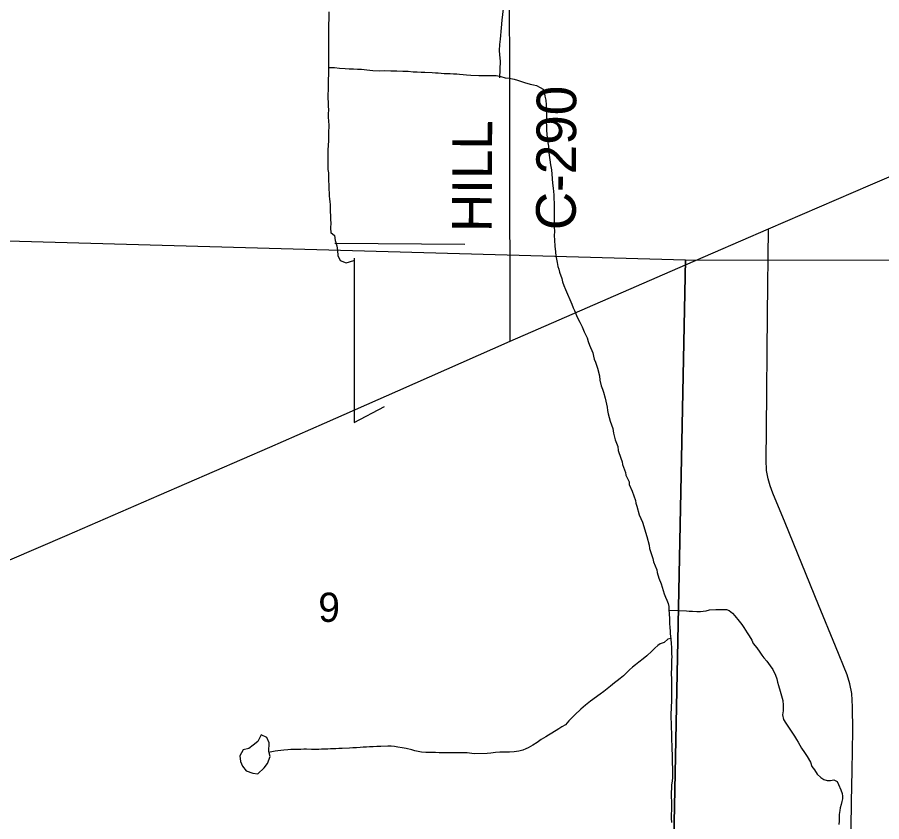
# Model space of a CAD drawing. Extents: x 0 to 34, y 0 to 22.
# Drawn here: x 4.264 to 4.883, y 14.576 to 15.153 of the extents above; entities that cross this region are included whole.
import ezdxf

# ---------------------------------------------------------------- set-up
doc = ezdxf.new("R2010")
doc.units = 0
for name, color, linetype in [('GM_X_Corporation', 7, 'Continuous'), ('GM_X_County_Road', 7, 'Continuous'), ('GM_X_County_Road_Text', 7, 'Continuous'), ('GM_X_Minor_Lake', 7, 'Continuous'), ('GM_X_Minor_River', 7, 'Continuous'), ('GM_X_Section_Text', 7, 'Continuous'), ('GM_X_US_Route', 7, 'Continuous')]:
    doc.layers.add(name, color=color, linetype=linetype)

msp = doc.modelspace()

# ---------------------------------------------------------------- linework, layer by layer
at = {"layer": 'GM_X_Corporation'}
for points in [[(4.23984, 14.99308), (4.74257, 14.97889), (4.73257, 14.48069), (4.23455, 14.48803)], [(4.74257, 14.97889), (5.23798, 14.97858), (5.23138, 14.47865), (4.73257, 14.48069)]]:
    msp.add_lwpolyline(points, close=True, dxfattribs=at)
at = {"layer": 'GM_X_County_Road'}
for points in [[(4.61689, 14.92059), (4.61615, 15.35746), (4.61648, 15.43754), (4.61654, 15.45161), (4.6166, 15.46574), (4.61662, 15.46991), (4.61665, 15.47577), (4.619, 15.48339), (4.62241, 15.49817)], [(4.85184, 14.1), (4.85975, 14.48173), (4.85986, 14.49169), (4.86024, 14.51707), (4.86084, 14.55277), (4.86154, 14.59063), (4.86185, 14.61297), (4.86234, 14.64168), (4.86224, 14.65865), (4.86175, 14.66812), (4.86031, 14.67517), (4.85828, 14.68159), (4.84997, 14.7022), (4.83787, 14.73162), (4.81382, 14.79042), (4.80519, 14.81174), (4.80313, 14.81706), (4.80176, 14.82197), (4.80064, 14.82807), (4.80036, 14.83565), (4.8005, 14.85746), (4.80134, 14.93992), (4.80188, 15.0011)]]:
    msp.add_lwpolyline(points, dxfattribs=at)
at = {"layer": 'GM_X_Minor_Lake'}
for points in [[(4.4441, 14.6266), (4.44445, 14.63292), (4.44267, 14.63677), (4.43873, 14.63859), (4.43632, 14.63391), (4.43301, 14.63116), (4.42972, 14.62879)], [(4.42972, 14.62879), (4.42571, 14.62795), (4.42331, 14.62365), (4.42376, 14.61946), (4.42537, 14.61618), (4.42794, 14.61288), (4.43263, 14.61104), (4.43623, 14.61074), (4.44091, 14.61497), (4.44308, 14.61814), (4.44512, 14.62302), (4.4441, 14.6266)]]:
    msp.add_lwpolyline(points, dxfattribs=at)
at = {"layer": 'GM_X_Minor_River'}
for p, q in [((4.49138, 14.99084), (4.58463, 14.99017)), ((4.50534, 14.98018), (4.50522, 14.86227)), ((4.50522, 14.86227), (4.5269, 14.87372)), ((4.50522, 14.86227), (4.50522, 14.86227))]:
    msp.add_line(p, q, dxfattribs=at)
for points in [[(4.48707, 15.15659), (4.4871, 15.15165), (4.48693, 15.14747), (4.48695, 15.14349), (4.48696, 15.14159), (4.48678, 15.13893), (4.48679, 15.13665), (4.48699, 15.13456), (4.48681, 15.13266), (4.48692, 15.11158), (4.48675, 15.10816), (4.48657, 15.1055), (4.4866, 15.10056), (4.48642, 15.09771), (4.48644, 15.09468), (4.48664, 15.09164), (4.48665, 15.08898), (4.48686, 15.08632), (4.48668, 15.08347), (4.48669, 15.081), (4.4871, 15.0755), (4.48711, 15.07341), (4.48693, 15.07151), (4.48696, 15.06581), (4.48678, 15.06372), (4.4866, 15.06163), (4.48644, 15.05688), (4.4865, 15.04359), (4.48689, 15.04131), (4.48692, 15.03543), (4.48713, 15.03258), (4.48714, 15.02954), (4.48735, 15.02669), (4.48736, 15.02441), (4.48756, 15.02251), (4.48776, 15.02043), (4.48796, 15.01853), (4.48797, 15.01663), (4.48817, 15.0134), (4.48838, 15.01074), (4.48839, 15.00808)], [(4.61187, 15.15867), (4.61106, 15.15052), (4.61053, 15.14522), (4.60973, 15.13707), (4.60943, 15.13328), (4.60912, 15.12892), (4.60941, 15.12568), (4.60985, 15.1213), (4.60933, 15.10918)], [(4.48689, 15.11671), (4.49107, 15.11672), (4.49468, 15.11617), (4.49885, 15.116), (4.5017, 15.11582), (4.50474, 15.11564), (4.50759, 15.11546), (4.51043, 15.11547), (4.51442, 15.11511), (4.5186, 15.11455), (4.52316, 15.11438), (4.52733, 15.11459), (4.53151, 15.11441), (4.53587, 15.11424), (4.54005, 15.11407), (4.54403, 15.11408), (4.54745, 15.11371), (4.55049, 15.11354), (4.55315, 15.11336), (4.5558, 15.11337), (4.56112, 15.11301), (4.56359, 15.11283), (4.56549, 15.11284), (4.56758, 15.11265), (4.56967, 15.11228), (4.57403, 15.1123), (4.5765, 15.11212), (4.57878, 15.11213), (4.58068, 15.11195), (4.58333, 15.11177), (4.5858, 15.11139), (4.58884, 15.11122), (4.59454, 15.11086), (4.59719, 15.11106), (4.60061, 15.11088), (4.60706, 15.11091), (4.61029, 15.11035), (4.61333, 15.10941), (4.61637, 15.10905), (4.61979, 15.1083), (4.62226, 15.10755), (4.62435, 15.1068), (4.6272, 15.10586), (4.63139, 15.10474), (4.63366, 15.10436), (4.63576, 15.1038), (4.63842, 15.10248), (4.64051, 15.10116), (4.64128, 15.09927), (4.64187, 15.09623), (4.64264, 15.09338), (4.64285, 15.08997), (4.6429, 15.08009), (4.64272, 15.07762), (4.64292, 15.07496), (4.64294, 15.07193), (4.64315, 15.06851), (4.64373, 15.06509), (4.64393, 15.06262), (4.64433, 15.06035), (4.64453, 15.0575), (4.64493, 15.05389), (4.64532, 15.05048), (4.64591, 15.04687), (4.6465, 15.04345), (4.64689, 15.04023), (4.64731, 15.03377), (4.6477, 15.03035), (4.6483, 15.02542), (4.64831, 15.02276), (4.64852, 15.01953), (4.64855, 15.01384), (4.64838, 15.0089), (4.64841, 15.00263), (4.64862, 14.99921), (4.64844, 14.99636), (4.64865, 14.99295), (4.64886, 14.98858), (4.64945, 14.98459), (4.64966, 14.98155), (4.65005, 14.97947), (4.65063, 14.977), (4.65121, 14.97415), (4.65179, 14.97226), (4.65237, 14.96998), (4.65391, 14.96543), (4.6545, 14.96315), (4.65546, 14.9605), (4.65661, 14.95765), (4.65796, 14.95424), (4.65968, 14.95045), (4.66122, 14.94704), (4.66218, 14.94457), (4.66295, 14.94268), (4.66506, 14.93775), (4.66679, 14.93415), (4.66851, 14.93092), (4.67005, 14.92732), (4.67216, 14.92296), (4.67293, 14.92031), (4.67389, 14.91765)], [(4.48839, 15.00808), (4.4886, 15.00486), (4.48842, 15.00201), (4.48844, 14.99802)], [(4.48844, 14.99851), (4.49124, 14.9963), (4.49171, 14.99287), (4.49293, 14.98904), (4.49321, 14.98561), (4.49349, 14.98199), (4.49528, 14.97833), (4.49961, 14.97687), (4.50504, 14.97845)], [(4.67389, 14.91765), (4.6762, 14.91234), (4.67659, 14.90988), (4.67717, 14.90779), (4.67813, 14.90551), (4.67948, 14.90134), (4.68084, 14.89584), (4.68123, 14.89261), (4.6822, 14.88863), (4.68316, 14.88616), (4.68393, 14.88408), (4.68509, 14.8799), (4.68645, 14.87326), (4.68666, 14.87098), (4.68724, 14.86852), (4.68859, 14.8634), (4.69052, 14.85809), (4.6911, 14.85467), (4.69227, 14.84993), (4.694, 14.84519), (4.69439, 14.84234), (4.69632, 14.83684), (4.69728, 14.83418), (4.69748, 14.83229), (4.69959, 14.8266), (4.6998, 14.82451), (4.7021, 14.81977), (4.7023, 14.81787), (4.70441, 14.81313), (4.70672, 14.8065), (4.70692, 14.8046), (4.70769, 14.80251), (4.70943, 14.79625), (4.71173, 14.79094), (4.71482, 14.7807), (4.71656, 14.77444), (4.71676, 14.77197), (4.71926, 14.76496), (4.71966, 14.76249), (4.72196, 14.7568), (4.72216, 14.7549), (4.72351, 14.75092), (4.72505, 14.74675), (4.72736, 14.73954), (4.72813, 14.73726), (4.72909, 14.73499), (4.73025, 14.73271), (4.73064, 14.73044), (4.73065, 14.72816), (4.73085, 14.7255), (4.73106, 14.72151), (4.73108, 14.71829), (4.73128, 14.71544), (4.73148, 14.71297), (4.73168, 14.71088), (4.73208, 14.70746), (4.73229, 14.70386), (4.73249, 14.70139), (4.73251, 14.69664), (4.73272, 14.69455), (4.73254, 14.69227), (4.73256, 14.68677), (4.7324, 14.68221), (4.7326, 14.67879), (4.73262, 14.67613), (4.73263, 14.67385), (4.73245, 14.671), (4.7325, 14.6617), (4.73232, 14.65961), (4.73234, 14.65695), (4.73216, 14.65429), (4.73221, 14.64328), (4.73242, 14.64005), (4.73245, 14.6353), (4.73285, 14.63037), (4.73286, 14.62771), (4.73307, 14.62486), (4.73315, 14.60796), (4.73297, 14.60549), (4.73242, 14.60283), (4.73243, 14.60017), (4.73226, 14.59751), (4.73227, 14.59371), (4.73248, 14.59125), (4.73251, 14.58422), (4.73233, 14.58232), (4.73235, 14.5789), (4.73255, 14.57586)], [(4.73067, 14.72782), (4.74318, 14.72745), (4.74508, 14.72727), (4.74754, 14.72709), (4.75077, 14.72691), (4.75324, 14.72692), (4.75514, 14.72711), (4.75741, 14.7275), (4.75969, 14.72808), (4.76424, 14.72848), (4.76671, 14.72849), (4.76974, 14.72831), (4.77202, 14.72832), (4.77392, 14.72757), (4.77621, 14.72587), (4.77793, 14.72379), (4.78098, 14.72), (4.78289, 14.71754), (4.78423, 14.71545), (4.78557, 14.71356), (4.78672, 14.71167), (4.78806, 14.70958), (4.78997, 14.70636), (4.79112, 14.70409), (4.79361, 14.70087), (4.79571, 14.69784), (4.79724, 14.69556), (4.79858, 14.69367), (4.80068, 14.6914), (4.80316, 14.68799), (4.80507, 14.68534), (4.80699, 14.68136), (4.80795, 14.67871), (4.80853, 14.67643), (4.80912, 14.67396), (4.81027, 14.66979), (4.81124, 14.66656), (4.81221, 14.66315), (4.81241, 14.65973), (4.81261, 14.65764), (4.81243, 14.65574), (4.81207, 14.65289), (4.81284, 14.64948), (4.81438, 14.64702), (4.81629, 14.64399), (4.81858, 14.64058), (4.8205, 14.63755), (4.82203, 14.63527), (4.82317, 14.63338), (4.82451, 14.63129), (4.82566, 14.62902), (4.82777, 14.62599), (4.82968, 14.62296), (4.83198, 14.61898), (4.83313, 14.61595), (4.83485, 14.61348), (4.83677, 14.61045), (4.83943, 14.608), (4.84172, 14.60667), (4.844, 14.60592), (4.84628, 14.60593), (4.84874, 14.60632), (4.85122, 14.60519), (4.85218, 14.60292), (4.85371, 14.59912), (4.85468, 14.59666), (4.85488, 14.59457), (4.85489, 14.59267), (4.85452, 14.59077), (4.85396, 14.58868), (4.8534, 14.58621), (4.85303, 14.58431), (4.85266, 14.58146), (4.85248, 14.57956), (4.8525, 14.5769), (4.85232, 14.57443)], [(4.73206, 14.70761), (4.73, 14.70708), (4.72716, 14.70479), (4.72451, 14.70383), (4.72262, 14.70268), (4.72054, 14.70077), (4.71846, 14.69849), (4.71487, 14.69524), (4.71222, 14.69314), (4.7092, 14.69066), (4.70674, 14.68876), (4.70466, 14.68704), (4.7024, 14.68513), (4.69805, 14.68075), (4.69578, 14.67884), (4.6937, 14.67731), (4.69181, 14.67578), (4.68879, 14.67349), (4.68652, 14.67159), (4.68406, 14.66968), (4.68142, 14.66777), (4.67461, 14.66261), (4.67102, 14.65975), (4.66762, 14.65689), (4.66327, 14.65288), (4.65893, 14.6485), (4.65666, 14.64583), (4.65402, 14.6443), (4.65175, 14.64277), (4.64683, 14.63972), (4.64455, 14.63838), (4.64247, 14.63723), (4.63907, 14.63513), (4.63623, 14.63303), (4.6332, 14.63112), (4.62999, 14.62921), (4.62809, 14.62844), (4.62601, 14.62767), (4.62317, 14.6269), (4.61994, 14.62632), (4.61653, 14.62612), (4.61311, 14.6261), (4.6097, 14.62609), (4.60647, 14.62589), (4.60325, 14.62549), (4.6004, 14.6251), (4.59148, 14.62507), (4.58958, 14.62525), (4.58616, 14.62562), (4.58351, 14.62561), (4.58066, 14.62579), (4.57478, 14.62576), (4.57174, 14.62575), (4.56623, 14.62573), (4.56358, 14.62591), (4.55655, 14.62588), (4.55352, 14.62625), (4.54877, 14.62718), (4.54649, 14.62793), (4.5425, 14.62868), (4.53965, 14.62923), (4.53661, 14.62979), (4.53414, 14.63016), (4.53186, 14.63053), (4.52939, 14.63052), (4.52446, 14.63012), (4.52161, 14.63011), (4.51877, 14.62991), (4.5163, 14.6299), (4.51402, 14.6297), (4.51175, 14.6297), (4.50947, 14.6295), (4.507, 14.6293), (4.50434, 14.62929), (4.50188, 14.62909), (4.49657, 14.62869), (4.49429, 14.62868), (4.4922, 14.62848), (4.48841, 14.62846), (4.48632, 14.62827), (4.48195, 14.62825), (4.48006, 14.62805), (4.47474, 14.62803), (4.47114, 14.62821), (4.46924, 14.6282), (4.46715, 14.628), (4.45994, 14.62797), (4.45785, 14.62778), (4.45482, 14.62757), (4.45064, 14.62718), (4.44875, 14.62698), (4.44401, 14.62601)]]:
    msp.add_lwpolyline(points, dxfattribs=at)
at = {"layer": 'GM_X_US_Route'}
for points in [[(4.48394, 14.86185), (4.53653, 14.88496), (4.61689, 14.92059), (4.74256, 14.97528), (4.80188, 15.0011), (4.87511, 15.03273), (4.95351, 15.06639), (5.02146, 15.0957), (5.11206, 15.13476), (5.23035, 15.18609), (5.31899, 15.22466), (5.46597, 15.28833), (5.57284, 15.32985), (5.62144, 15.34871), (5.74871, 15.39965), (5.82206, 15.42868), (5.9013, 15.458), (5.98911, 15.49306)], [(3.23544, 14.76821), (3.25461, 14.76884), (3.25942, 14.76899), (3.30374, 14.76675), (3.39532, 14.76156), (3.45885, 14.75792), (3.59139, 14.75076), (3.69755, 14.74417), (3.76243, 14.74023), (3.85528, 14.74121), (3.99777, 14.74219), (4.11852, 14.74233), (4.18416, 14.74275), (4.20422, 14.74345), (4.21445, 14.74566), (4.22357, 14.74864), (4.23844, 14.75509), (4.25877, 14.76386), (4.29979, 14.78174), (4.36557, 14.81021), (4.44495, 14.84471), (4.48394, 14.86185)]]:
    msp.add_lwpolyline(points, dxfattribs=at)

# ---------------------------------------------------------------- texts
at = {"layer": 'GM_X_County_Road_Text'}
for s, rotation, p in [('C-290', 89.72363, (4.6639, 15.00007)), ('HILL', 89.69746, (4.60372, 14.9987))]:
    msp.add_text(s, height=0.028409, rotation=rotation, dxfattribs=at).set_placement(p)
at = {"layer": 'GM_X_Section_Text'}
msp.add_text('9', height=0.02093, rotation=0.00001, dxfattribs=at).set_placement((4.47954, 14.71951))

doc.saveas('drawing.dxf')
